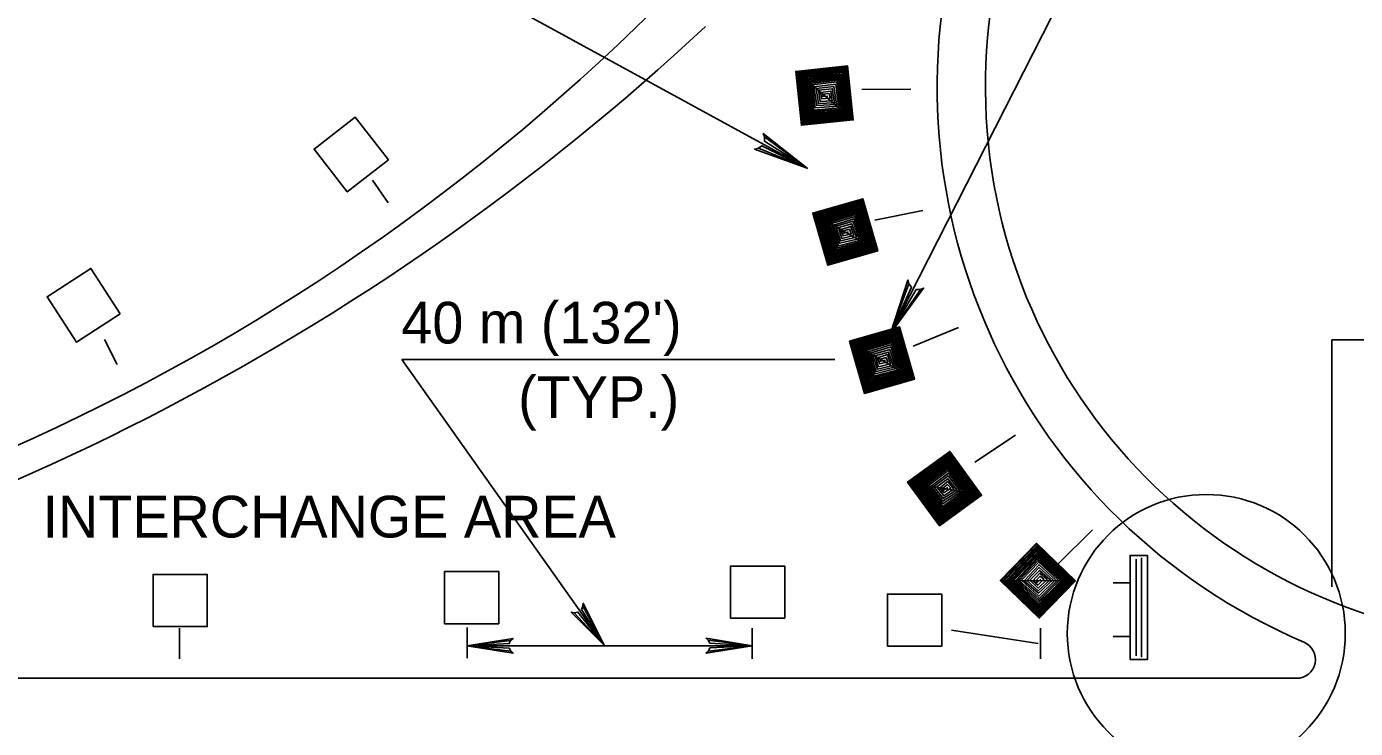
# Model space of a CAD drawing. Extents: x 640253 to 641999, y 298458 to 299646.
# Drawn here: x 641432.2 to 641527.8, y 299419 to 299469.5 of the extents above; entities that cross this region are included whole.
import ezdxf

# ---------------------------------------------------------------- set-up
doc = ezdxf.new("R2010")
doc.units = 0
doc.layers.add('2', color=7, linetype='Continuous')

msp = doc.modelspace()

# ---------------------------------------------------------------- linework, layer by layer
at = {"layer": '2'}
for p, q in [((641436.084, 299487.935), (641488.371, 299459.326)), ((641514.744, 299487.506), (641494.371, 299447.447)), ((641495.829, 299465.014), (641492.288, 299464.995)), ((641497.721, 299465.014), (641497.721, 299465.014)), ((641458.233, 299456.839), (641457.088, 299458.47)), ((641498.554, 299456.647), (641498.554, 299456.647)), ((641496.698, 299456.283), (641493.244, 299455.589)), ((641501.002, 299448.593), (641501.002, 299448.593)), ((641499.248, 299447.864), (641495.986, 299446.529)), ((641438.725, 299445.21), (641437.823, 299446.997)), ((641526.117, 299429.206), (641526.117, 299446.979)), ((641526.117, 299446.979), (641550.713, 299446.979)), ((641473.752, 299425.022), (641459.215, 299445.558)), ((641459.215, 299445.558), (641490.363, 299445.558)), ((641504.942, 299441.164), (641504.942, 299441.164)), ((641503.363, 299440.122), (641500.429, 299438.179)), ((641510.252, 299434.639), (641510.252, 299434.639)), ((641508.9, 299433.302), (641506.4, 299430.837)), ((641512.021, 299424.249), (641512.021, 299431.197)), ((641512.417, 299424.147), (641512.417, 299431.297)), ((641511.621, 299429.497), (641510.371, 299429.497)), ((641443.202, 299424.033), (641443.202, 299426.237)), ((641463.914, 299424.068), (641463.914, 299426.273)), ((641484.409, 299424.033), (641484.409, 299426.237)), ((641498.746, 299426.099), (641504.977, 299425.143)), ((641505.15, 299424.033), (641505.15, 299426.237)), ((641511.621, 299425.647), (641510.371, 299425.647)), ((641484.409, 299424.97), (641463.892, 299424.97)), ((641394.898, 299422.627), (641523.584, 299422.627))]:
    msp.add_line(p, q, dxfattribs=at)
for points in [[(641491.677, 299462.812), (641491.267, 299466.691), (641487.544, 299466.297), (641487.954, 299462.418), (641491.677, 299462.812), (641487.615, 299466.241), (641488.013, 299462.493), (641491.621, 299462.874), (641491.221, 299466.622), (641487.684, 299466.249), (641488.069, 299462.574), (641491.542, 299462.941), (641491.165, 299466.537), (641487.781, 299466.172), (641488.154, 299462.649), (641491.477, 299463.004), (641491.113, 299466.466), (641487.846, 299466.118), (641488.204, 299462.726), (641491.413, 299463.066), (641491.056, 299466.383), (641487.923, 299466.039), (641488.265, 299462.804), (641491.35, 299463.118), (641490.992, 299466.306), (641488.006, 299465.97), (641488.331, 299462.879), (641491.275, 299463.179), (641490.931, 299466.231), (641488.084, 299465.91), (641488.396, 299462.952), (641491.19, 299463.229), (641490.863, 299466.133), (641488.177, 299465.849), (641488.463, 299463.049), (641491.135, 299463.293), (641490.796, 299466.031), (641488.246, 299465.766), (641488.523, 299463.133), (641491.061, 299463.36), (641490.746, 299465.945), (641488.311, 299465.689), (641488.592, 299463.218), (641491.013, 299463.435), (641490.688, 299465.849), (641488.4, 299465.599), (641488.671, 299463.316), (641489.769, 299463.383), (641490.934, 299463.506), (641490.619, 299465.764), (641488.508, 299465.514), (641488.769, 299463.404), (641490.85, 299463.583), (641490.559, 299465.67), (641488.594, 299465.435), (641488.854, 299463.518), (641490.75, 299463.683), (641490.506, 299465.537), (641488.731, 299465.329), (641488.948, 299463.666), (641490.613, 299463.787), (641490.417, 299465.383), (641488.852, 299465.197), (641489.056, 299463.835), (641490.483, 299463.91), (641490.481, 299463.916), (641490.292, 299465.222), (641489.013, 299465.077), (641489.169, 299463.983), (641490.338, 299464.039), (641490.173, 299465.052), (641489.184, 299464.958), (641489.29, 299464.137), (641490.169, 299464.191), (641490.067, 299464.883), (641489.331, 299464.779), (641489.409, 299464.318), (641490.01, 299464.36), (641489.946, 299464.697), (641489.502, 299464.649), (641489.488, 299464.499), (641489.848, 299464.518)], [(641485.298, 299461.584), (641485.288, 299461.276), (641488.371, 299459.326), (641485.298, 299461.584), (641485.209, 299461.823), (641488.371, 299459.326), (641485.105, 299460.942), (641484.856, 299460.77), (641488.371, 299459.326), (641484.588, 299460.712), (641484.856, 299460.77)], [(641493.444, 299453.387), (641492.367, 299457.135), (641488.769, 299456.099), (641489.846, 299452.351), (641493.444, 299453.387), (641488.848, 299456.058), (641489.892, 299452.435), (641493.379, 299453.437), (641492.336, 299457.06), (641488.915, 299456.077), (641489.934, 299452.524), (641493.29, 299453.489), (641492.292, 299456.964), (641489.025, 299456.02), (641490.002, 299452.614), (641493.215, 299453.539), (641492.254, 299456.885), (641489.098, 299455.976), (641490.04, 299452.699), (641493.14, 299453.589), (641492.213, 299456.793), (641489.188, 299455.912), (641490.086, 299452.785), (641493.069, 299453.629), (641492.163, 299456.708), (641489.281, 299455.858), (641490.14, 299452.87), (641492.986, 299453.677), (641492.117, 299456.622), (641489.367, 299455.812), (641490.188, 299452.954), (641492.894, 299453.712), (641492.067, 299456.516), (641489.471, 299455.77), (641490.238, 299453.062), (641492.827, 299453.764), (641492.019, 299456.401), (641489.552, 299455.699), (641490.284, 299453.154), (641492.742, 299453.818), (641491.983, 299456.31), (641489.629, 299455.635), (641490.336, 299453.249), (641492.681, 299453.885), (641491.944, 299456.206), (641489.733, 299455.562), (641490.398, 299453.36), (641491.467, 299453.616), (641492.594, 299453.939), (641491.89, 299456.11), (641489.854, 299455.495), (641490.479, 299453.464), (641492.496, 299454.002), (641491.848, 299456.008), (641489.952, 299455.433), (641490.542, 299453.591), (641492.381, 299454.081), (641491.819, 299455.866), (641490.106, 299455.354), (641490.608, 299453.754), (641492.227, 299454.16), (641491.756, 299455.697), (641490.25, 299455.243), (641490.686, 299453.937), (641492.077, 299454.26), (641492.075, 299454.266), (641491.663, 299455.518), (641490.427, 299455.154), (641490.771, 299454.104), (641491.913, 299454.36), (641491.573, 299455.331), (641490.617, 299455.064), (641490.863, 299454.274), (641491.719, 299454.481), (641491.498, 299455.145), (641490.792, 299454.914), (641490.948, 299454.474), (641491.535, 299454.62), (641491.41, 299454.941), (641490.983, 299454.816), (641490.996, 299454.668), (641491.346, 299454.747)], [(641496.51, 299450.606), (641496.202, 299450.604), (641494.371, 299447.447), (641496.51, 299450.606), (641496.746, 299450.702), (641494.371, 299447.447), (641495.861, 299450.774), (641495.679, 299451.014), (641494.371, 299447.447), (641495.611, 299451.279), (641495.679, 299451.014)], [(641496.088, 299444.162), (641495.01, 299447.908), (641491.413, 299446.877), (641492.49, 299443.127), (641496.088, 299444.162), (641491.492, 299446.835), (641492.535, 299443.208), (641496.023, 299444.212), (641494.979, 299447.835), (641491.559, 299446.854), (641492.577, 299443.302), (641495.934, 299444.264), (641494.936, 299447.739), (641491.669, 299446.795), (641492.646, 299443.391), (641495.858, 299444.314), (641494.898, 299447.66), (641491.742, 299446.754), (641492.684, 299443.474), (641495.784, 299444.364), (641494.856, 299447.568), (641491.831, 299446.687), (641492.729, 299443.562), (641495.713, 299444.406), (641494.806, 299447.483), (641491.925, 299446.633), (641492.784, 299443.647), (641495.629, 299444.452), (641494.76, 299447.399), (641492.01, 299446.587), (641492.831, 299443.731), (641495.538, 299444.487), (641494.711, 299447.293), (641492.115, 299446.547), (641492.881, 299443.839), (641495.471, 299444.541), (641494.663, 299447.177), (641492.196, 299446.472), (641492.927, 299443.929), (641495.385, 299444.595), (641494.627, 299447.087), (641492.273, 299446.41), (641492.979, 299444.024), (641495.325, 299444.66), (641494.588, 299446.981), (641492.377, 299446.339), (641493.042, 299444.137), (641494.111, 299444.391), (641495.238, 299444.716), (641494.534, 299446.885), (641492.498, 299446.27), (641493.123, 299444.241), (641495.14, 299444.776), (641494.492, 299446.785), (641492.596, 299446.208), (641493.186, 299444.366), (641495.025, 299444.856), (641494.465, 299446.643), (641492.75, 299446.131), (641493.252, 299444.531), (641494.871, 299444.937), (641494.4, 299446.472), (641492.894, 299446.018), (641493.329, 299444.714), (641494.721, 299445.035), (641494.719, 299445.041), (641494.306, 299446.295), (641493.071, 299445.931), (641493.415, 299444.879), (641494.556, 299445.135), (641494.217, 299446.106), (641493.26, 299445.841), (641493.506, 299445.049), (641494.363, 299445.258), (641494.142, 299445.92), (641493.436, 299445.689), (641493.592, 299445.252), (641494.179, 299445.395), (641494.054, 299445.716), (641493.629, 299445.593), (641493.64, 299445.443), (641493.99, 299445.524)], [(641500.915, 299435.797), (641498.621, 299438.949), (641495.592, 299436.749), (641497.888, 299433.593), (641500.915, 299435.797), (641495.681, 299436.735), (641497.904, 299433.687), (641500.838, 299435.822), (641498.615, 299438.872), (641495.742, 299436.776), (641497.913, 299433.789), (641500.736, 299435.841), (641498.608, 299438.764), (641495.861, 299436.76), (641497.942, 299433.893), (641500.648, 299435.862), (641498.6, 299438.679), (641495.944, 299436.745), (641497.95, 299433.987), (641500.561, 299435.883), (641498.592, 299438.577), (641496.052, 299436.712), (641497.963, 299434.083), (641500.479, 299435.897), (641498.575, 299438.479), (641496.159, 299436.695), (641497.986, 299434.183), (641500.385, 299435.912), (641498.559, 299438.385), (641496.252, 299436.683), (641498.002, 299434.276), (641500.285, 299435.914), (641498.548, 299438.268), (641496.365, 299436.679), (641498.013, 299434.395), (641500.206, 299435.943), (641498.542, 299438.143), (641496.467, 299436.639), (641498.025, 299434.497), (641500.108, 299435.964), (641498.542, 299438.045), (641496.561, 299436.604), (641498.04, 299434.604), (641500.027, 299436.004), (641498.542, 299437.933), (641496.686, 299436.574), (641498.061, 299434.731), (641498.979, 299435.335), (641499.927, 299436.024), (641498.523, 299437.824), (641496.821, 299436.549), (641498.102, 299434.856), (641499.813, 299436.049), (641498.517, 299437.714), (641496.934, 299436.526), (641498.117, 299434.997), (641499.681, 299436.087), (641498.54, 299437.572), (641497.104, 299436.504), (641498.125, 299435.172), (641499.506, 299436.11), (641498.538, 299437.391), (641497.279, 299436.449), (641498.135, 299435.372), (641499.331, 299436.151), (641499.329, 299436.154), (641498.51, 299437.191), (641497.475, 299436.427), (641498.156, 299435.556), (641499.144, 299436.189), (641498.492, 299436.983), (641497.686, 299436.406), (641498.186, 299435.749), (641498.919, 299436.235), (641498.483, 299436.783), (641497.9, 299436.324), (641498.198, 299435.966), (641498.7, 299436.304), (641498.471, 299436.562), (641498.115, 299436.302), (641498.177, 299436.164), (641498.479, 299436.358)], [(641507.665, 299429.643), (641504.858, 299432.349), (641502.256, 299429.658), (641505.065, 299426.947), (641507.665, 299429.643), (641502.348, 299429.658), (641505.065, 299427.041), (641507.584, 299429.654), (641504.865, 299432.27), (641502.398, 299429.712), (641505.056, 299427.143), (641507.479, 299429.656), (641504.877, 299432.164), (641502.521, 299429.716), (641505.067, 299427.252), (641507.39, 299429.66), (641504.883, 299432.079), (641502.604, 299429.714), (641505.059, 299427.347), (641507.3, 299429.666), (641504.896, 299431.976), (641502.717, 299429.699), (641505.054, 299427.445), (641507.217, 299429.666), (641504.894, 299431.877), (641502.825, 299429.702), (641505.059, 299427.545), (641507.123, 299429.664), (641504.896, 299431.783), (641502.921, 299429.706), (641505.059, 299427.641), (641507.025, 299429.649), (641504.904, 299431.666), (641503.029, 299429.72), (641505.05, 299427.758), (641506.942, 299429.664), (641504.921, 299431.541), (641503.135, 299429.699), (641505.044, 299427.862), (641506.84, 299429.666), (641504.938, 299431.445), (641503.236, 299429.685), (641505.04, 299427.968), (641506.754, 299429.693), (641504.956, 299431.335), (641503.365, 299429.674), (641505.04, 299428.097), (641505.838, 299428.851), (641506.652, 299429.695), (641504.956, 299431.224), (641503.502, 299429.674), (641505.056, 299428.226), (641506.535, 299429.704), (641504.971, 299431.116), (641503.615, 299429.668), (641505.048, 299428.37), (641506.4, 299429.714), (641505.019, 299430.981), (641503.79, 299429.679), (641505.025, 299428.543), (641506.225, 299429.708), (641505.046, 299430.799), (641503.971, 299429.654), (641505, 299428.743), (641506.044, 299429.716), (641506.04, 299429.72), (641505.054, 299430.597), (641504.169, 299429.666), (641504.99, 299428.927), (641505.852, 299429.722), (641505.071, 299430.391), (641504.377, 299429.681), (641504.986, 299429.122), (641505.623, 299429.726), (641505.098, 299430.191), (641504.606, 299429.639), (641504.959, 299429.337), (641505.394, 299429.758), (641505.127, 299429.972), (641504.819, 299429.654), (641504.904, 299429.529), (641505.169, 299429.772)], [(641472.228, 299427.82), (641472.125, 299427.591), (641473.752, 299425.022), (641472.228, 299427.82), (641472.258, 299428.026), (641473.752, 299425.022), (641471.87, 299427.399), (641471.616, 299427.349), (641473.752, 299425.022), (641471.396, 299427.398), (641471.616, 299427.349)], [(641467.05, 299424.57), (641466.929, 299424.795), (641463.892, 299424.97), (641467.05, 299424.57), (641467.206, 299424.433), (641463.892, 299424.97), (641466.929, 299425.127), (641467.033, 299425.351), (641463.892, 299424.97), (641467.206, 299425.491), (641467.033, 299425.351)], [(641481.25, 299425.37), (641481.371, 299425.145), (641484.409, 299424.97), (641481.25, 299425.37), (641481.094, 299425.508), (641484.409, 299424.97), (641481.371, 299424.814), (641481.267, 299424.589), (641484.409, 299424.97), (641481.094, 299424.449), (641481.267, 299424.589)]]:
    msp.add_lwpolyline(points, dxfattribs=at)
for points in [[(641458.244, 299459.935), (641455.848, 299463.006), (641452.89, 299460.706), (641455.285, 299457.631)], [(641438.954, 299448.849), (641436.836, 299452.116), (641433.688, 299450.083), (641435.806, 299446.812)], [(641511.592, 299423.972), (641511.592, 299431.47), (641512.846, 299431.47), (641512.846, 299423.972)], [(641441.311, 299426.351), (641445.209, 299426.351), (641445.209, 299430.099), (641441.311, 299430.099)], [(641462.281, 299426.554), (641466.179, 299426.554), (641466.179, 299430.302), (641462.281, 299430.302)], [(641482.85, 299426.956), (641486.748, 299426.956), (641486.748, 299430.704), (641482.85, 299430.704)], [(641494.144, 299424.939), (641498.042, 299424.939), (641498.042, 299428.687), (641494.144, 299428.687)]]:
    msp.add_lwpolyline(points, close=True, dxfattribs=at)
msp.add_circle((641517.079, 299425.854), 10, dxfattribs=at)
for centre, radius, start, end in [((641541.114, 299465.152), 43.393, 80.04779, 246.92178), ((641541.114, 299465.152), 39.921, 13.53946, 270), ((641368.281, 299580.998), 155.099, 272.37756, 315.38102), ((641360.297, 299598.993), 177.042, 281.18464, 313.00346), ((641523.576, 299423.983), 1.356, 270, 66.92608)]:
    msp.add_arc(centre, radius, start, end, dxfattribs=at)

# ---------------------------------------------------------------- texts
for s, p in [("40 m (132')", (641459.17, 299446.719)), ('(TYP.)', (641467.574, 299441.357)), ('INTERCHANGE AREA', (641433.361, 299432.76))]:
    msp.add_text(s, height=3, dxfattribs=at).set_placement(p)

doc.saveas('drawing.dxf')
